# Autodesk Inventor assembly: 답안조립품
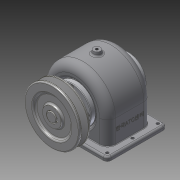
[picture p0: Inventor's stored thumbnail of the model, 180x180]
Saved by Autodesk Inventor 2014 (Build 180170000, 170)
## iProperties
Created: 2015-09
Part Number: 답안조립품
Document SubType Name: Assembly
Designer: basic
Author: basic
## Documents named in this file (14)
- C:\Users\basic\Desktop\450907V1020\답안조립품.iam
- C:\Users\basic\Desktop\450907V1020\본체.ipt
- C:\Users\basic\Desktop\450907V1020\축.ipt
- C:\Users\basic\Desktop\450907V1020\키 - 5 x 5 x 18.ipt
- C:\Users\basic\Desktop\450907V1020\키 - 6 x 6 x 22.ipt
- C:\Users\basic\Desktop\450907V1020\베어링 6203.ipt
- C:\Users\basic\Desktop\450907V1020\뒤커버.ipt
- C:\Users\basic\Desktop\450907V1020\볼트 M3 x 8.ipt
- C:\Users\basic\Desktop\450907V1020\앞커버.ipt
- C:\Users\basic\Desktop\450907V1020\볼트 M3 x 10.ipt
- C:\Users\basic\Desktop\450907V1020\스퍼기어.ipt
- C:\Users\basic\Desktop\450907V1020\V-벨트풀리.ipt
- C:\Users\basic\Desktop\450907V1020\멈춤나사 - M4x10.ipt
- C:\Users\basic\Desktop\450907V1020\오일 실 17 32 8.ipt
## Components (9 placed, 3 different names)
1. V-벨트풀리:1
2. ISO 4762 M3 x 8:1
3. ISO 4762 M3 x 8:2
4. ISO 4762 M3 x 8:3
5. ISO 4762 M3 x 8:4
6. ISO 4762 M3 x 10:1
7. ISO 4762 M3 x 10:2
8. ISO 4762 M3 x 10:3
9. ISO 4762 M3 x 10:4
